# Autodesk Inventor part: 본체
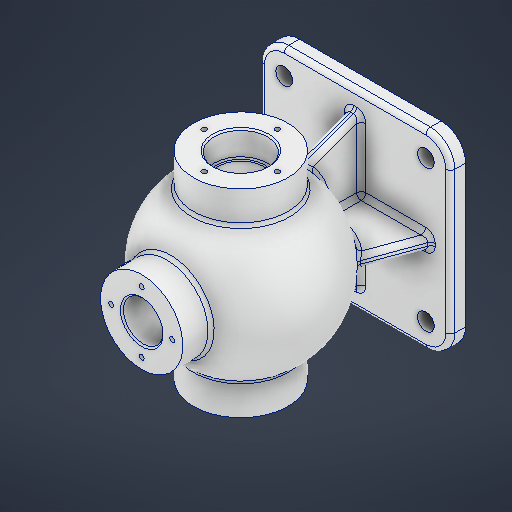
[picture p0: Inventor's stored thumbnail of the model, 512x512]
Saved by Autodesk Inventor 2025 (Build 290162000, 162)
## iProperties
Created: 2025-08
Part Number: 본체
Material: 알루미늄 6061
Document SubType Name: Modeling
Designer: infra006
Density: 2.7 g/cm^3
Appearance: 알루미늄 - 평지
Mass: 1536.91 g
Surface Area: 1167.84 cm^2
Volume: 569.226 cm^3
Author: infra006
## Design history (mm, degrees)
sketch "스케치1"
  geometry: L1 (-46.5, 62.5)-(46.5, 62.5); L2 (62.5, 46.5)-(62.5, -46.5); L3 (46.5, -62.5)-(-46.5, -62.5); L4 (-62.5, -46.5)-(-62.5, 46.5); L5 (-62.5, 62.5)-(62.5, -62.5); L6 (62.5, 62.5)-(-62.5, -62.5); A1 r 16 centre (-46.5, 46.5) between (-46.5, 62.5) and (-62.5, 46.5); A2 r 16 centre (-46.5, -46.5) between (-62.5, -46.5) and (-46.5, -62.5); A3 r 16 centre (46.5, -46.5) between (46.5, -62.5) and (62.5, -46.5); A4 r 16 centre (46.5, 46.5) between (62.5, 46.5) and (46.5, 62.5); 1 further point
  constraints: 12 end point, 8 point on circle, 8 point on line, 8 tangent, 4 centre point, 3 equal radius, 2 midpoint, 2 parallel, 1 horizontal, 1 perpendicular
  dimensions: "d0" = 125 distance of L5.end L6.end; "d1" = 125 distance of L6.start L5.end; "d2" = 16 radius of A1
extrude "돌출1" new body sketch "스케치1" distance "d3" = 10; taper "d4" = 0 deg
node "작업 평면1"
sketch "스케치2"
  geometry: L1 (-54, 0)-(54, 0); L2 (62.5, -46.5)-(62.5, 46.5) reference; L3 (46.5, 62.5)-(-46.5, 62.5) reference; A1 r 54 centre (0, 0) between (-54, 0) and (54, 0); 1 further point
  constraints: 2 end point, 2 point on circle, 1 centre point, 1 coincident, 1 perpendicular
  dimensions: "d8" = 108 diameter of A1; "d9" = 62.5 distance between parallel lines of L3 L1
revolve "회전1" sketch "스케치2" stored, may be unused: angle "d10" = 90 deg
sketch "스케치3"
  geometry: L1 (46.5, 10)-(-46.5, 10) reference; L2 (-37.385, 46.034)-(-50.5, 10); L3 (37.385, 46.034)-(50.5, 10); L4 (62.5, 0)-(62.5, 10) reference; L5 (-62.5, 0)-(-62.5, 10) reference; L6 (37.385, 46.034)-(-37.385, 46.034); L7 (-50.5, 10)-(50.5, 10); L8 (-46.5, 10)-(-62.5, 10) reference; C1 r 54 at (0, 85) reference; A1 r 54 centre (0, 85) between (-37.385, 46.034) and (37.385, 46.034) reference; 5 further points
  constraints: 8 end point, 2 point on circle, 2 point on line, 1 collinear
  dimensions: "d11" = 12 distance from line of L4 L3.end; "d12" = 12 distance from line of L5 L2.end; "d13" = 20 deg angle of L4 L3; "d14" = 20 deg angle of L5 L2
extrude "돌출2" join sketch "스케치3" stored distance "d15" = 8; taper "d16" = 0 deg
sketch "스케치4"
  geometry: L1 (-46.5, 10)-(46.5, 10) reference; L2 (-46.5, 10)-(-62.5, 10) reference; L3 (-37.385, 46.034)-(-50.5, 10); L4 (-62.5, 0)-(-62.5, 10) reference; L5 (37.385, 46.034)-(50.5, 10); L6 (62.5, 0)-(62.5, 10) reference; C1 r 54 at (0, 85) reference; A1 r 54 centre (0, 85) between (-37.385, 46.034) and (37.385, 46.034) reference; 2 further points
  constraints: 4 end point, 2 point on circle, 2 point on line
  dimensions: "d17" = 12 distance from line of L4 L3.end; "d18" = 20 deg angle of L4 L3; "d19" = 12 distance from line of L6 L5.end; "d20" = 20 deg angle of L6 L5
feature "리브1" dims "d21" = 1, "d22" = 8, "d23" = 0, "d24" = 0, "d25" = 1, "d26" = 1
feature "리브2" dims "d27" = 1, "d28" = 8, "d29" = 0, "d30" = 0, "d31" = 1, "d32" = 1
node "작업 평면2"
sketch "스케치7"
  geometry: L1 (65, 116)-(-65, 116); L2 (-65, 116)-(-65, 54); L3 (-65, 54)-(65, 54); L4 (65, 54)-(65, 116); L5 (46.5, 0)-(-46.5, 0) reference; L6 (65, 85)-(-65, 85); L7 (65, 102.5)-(49, 102.5); L8 (49, 102.5)-(49, 100); L9 (49, 100)-(-49, 100); L10 (-49, 102.5)-(-65, 102.5); L11 (-49, 102.5)-(-49, 100); 2 further points
  constraints: 20 end point, 4 parallel, 3 midpoint, 2 horizontal, 2 perpendicular, 2 point on line, 2 vertical
  dimensions: "d38" = 130 distance of L3.end L2.end; "d39" = 62 distance of L2.end L1.end; "d40" = 54 distance between parallel lines of L5 L3; "d41" = 65 distance from line of point (0, 0) L2; "d42" = 17.5 distance between parallel lines of L6 L7; "d43" = 16 distance of L7.start L7.end; "d44" = 2.5 distance of L7.end L8.end; "d45" = 16 distance between parallel lines of L2 L11; "d46" = 17.5 distance between parallel lines of L6 L10
sketch "스케치8"
  geometry: L1 (65, 116)-(-65, 116) reference; L2 (-65, 116)-(-65, 54) reference; L3 (-49, 102.5)-(-65, 102.5) reference; L4 (-49, 102.5)-(-49, 100) reference; L5 (49, 100)-(-49, 100) reference; L6 (49, 102.5)-(49, 100) reference; L7 (65, 102.5)-(49, 102.5) reference; L8 (65, 54)-(65, 116) reference; L9 (65, 85)-(-65, 85) reference; 1 further point
revolve "회전3" stored, may be unused: angle "d47" = 90 deg
sketch "스케치9"
  geometry: L1 (27, 150)-(-27, 150); L2 (46.5, 0)-(-46.5, 0) reference; L3 (27, 150)-(27, 92.205); L4 (27, 92.205)-(-27, 92.205); L5 (-27, 92.205)-(-27, 150); L6 (13, 150)-(13, 92.205); L7 (-13, 150)-(-13, 92.205); L8 (0, 150)-(0, 92.205); 2 further points
  constraints: 14 end point, 4 point on line, 3 midpoint, 2 perpendicular, 2 vertical, 1 horizontal, 1 parallel
  dimensions: "d48" = 150 distance between parallel lines of L2 L1; "d49" = 54 distance of L1.start L1.end; "d50" = 27 horizontal distance of point (0, 0) L1.end; "d51" = 13 distance from line of L8.start L6; "d52" = 26 distance between parallel lines of L6 L7; "d60" = 57.7948 distance between parallel lines of L1 L4
revolve "회전4" stored, may be unused: angle "d53" = 90 deg
sketch "스케치10" dims "d54" = 88
  geometry: L1 (44, 0)-(-95.364, 0); 3 further points
  constraints: 2 end point, 1 coincident, 1 horizontal, 3 other
  dimensions: "d55" = 139.36443 distance of L1.start L1.end; "d56" = 0 distance from line of point (0, 0) L1
revolve "회전5" sketch "스케치10" stored, may be unused: angle "d57" = 90 deg
revolve "회전6" stored, may be unused: angle "d58" = 90 deg
revolve "회전7" stored, may be unused: angle "d59" = 90 deg
sketch "스케치11"
  geometry: L1 (-46.5, -85)-(46.5, -85) reference; L2 (62.5, -85)-(62.5, -75) reference; L3 (0, 24)-(0, -24); L4 (-24, 0)-(24, 0); A1 r 24 centre (0, 0) between (0, 24) and (0, -24); 5 further points
  constraints: 4 coincident, 4 end point, 4 point on circle, 1 centre point, 1 horizontal, 1 vertical
  dimensions: "d61" = 48 diameter of A1; "d62" = 85 distance from line of L1 A1.centre; "d63" = 62.5 distance from line of L2 A1.centre; "d64" = 48 distance of L3.start L3.end; "d65" = 48 distance of L4.start L4.end
hole "구멍1" sketch "스케치11" at (0, 24), (-24, 0), (0, -24), (24, 0) diameter "d66" = 3.242; stored, may be unused: countersink angle "d70" = 90 deg, drill point angle "d72" = 118 deg; dims "d67" = 12, "d68" = 4, "d69" = 2, "d71" = 15
sketch "스케치12"
  geometry: L1 (46.5, 85)-(-46.5, 85) reference; L2 (-62.5, 85)-(-62.5, 75) reference; L3 (0, -24)-(0, 24); L4 (24, 0)-(-24, 0); C1 r 1.621 at (0, 24) reference; C2 r 1.621 at (24, 0) reference; C3 r 1.621 at (0, -24) reference; A1 r 24 centre (0, 0) between (0, -24) and (-24, 0); 5 further points
  constraints: 4 coincident, 4 end point, 2 point on circle, 1 centre point, 1 horizontal, 1 vertical
  dimensions: "d73" = 48 diameter of A1; "d74" = 85 distance from line of L1 A1.centre; "d75" = 62.5 distance from line of L2 A1.centre
hole "구멍2" sketch "스케치12" at (0, -24), (24, 0), (0, 24), (-24, 0) diameter "d76" = 3.242; stored, may be unused: countersink angle "d80" = 90 deg, drill point angle "d82" = 118 deg; dims "d77" = 12, "d78" = 4, "d79" = 2, "d81" = 15
sketch "스케치13"
  geometry: L1 (0, -20)-(0, 20); L2 (-4, 0)-(-37.385, 0) reference; L3 (-20, 0)-(20, 0); A1 r 20 centre (0, 0) between (0, -20) and (0, 20); 5 further points
  constraints: 5 coincident, 4 end point, 4 point on circle, 2 point on line, 1 centre point, 1 perpendicular
  dimensions: "d83" = 40 diameter of A1; "d84" = 40 distance of L1.start L1.end
hole "구멍3" sketch "스케치13" at (0, -20), (20, 0), (0, 20), (-20, 0) diameter "d85" = 3.242; stored, may be unused: countersink angle "d89" = 90 deg, drill point angle "d91" = 118 deg; dims "d86" = 9, "d87" = 4, "d88" = 2, "d90" = 11
node "작업 평면3"
sketch "스케치14"
  geometry: L1 (-14.253, 146.239)-(14.253, 146.239); L2 (14.253, 146.239)-(14.253, 135.761); L3 (14.253, 135.761)-(-14.253, 135.761); L4 (-14.253, 135.761)-(-14.253, 146.239); L5 (-14.253, 141)-(14.253, 141); L6 (0, 146.239)-(0, 135.761); L7 (27, 150)-(-27, 150) reference; L8 (65, 116)-(65, 54) reference; 1 further point
  constraints: 4 end point, 4 midpoint, 2 other
  dimensions: "d93" = 9 distance between parallel lines of L5 L7; "d94" = 65 distance between parallel lines of L8 L6
feature "엠보싱1" sketch "스케치14" dims "d95" = 0.5, "d96" = 0
chamfer "모따기1" distance "d97" = 1; stored, may be unused: second distance "d98" = 2, angle "d99" = 45 deg
chamfer "모따기2" distance "d100" = 1; stored, may be unused: second distance "d101" = 2, angle "d102" = 45 deg
fillet "모깎기1" dims "d103" = 0.6
chamfer "모따기3" distance "d104" = 1; stored, may be unused: second distance "d105" = 2, angle "d106" = 45 deg
feature "면 삭제1"
feature "면 삭제2"
fillet "모깎기2" dims "d107" = 3
fillet "모깎기3" dims "d108" = 3
feature "면 삭제3"
feature "면 삭제4"
fillet "모깎기4" dims "d109" = 3
fillet "모깎기5" dims "d110" = 3
fillet "모깎기6" dims "d111" = 3
sketch "스케치15"
  geometry: L1 (46.5, 46.5)-(-46.5, 46.5); L2 (-46.5, 46.5)-(-46.5, -46.5); L3 (-46.5, -46.5)-(46.5, -46.5); L4 (46.5, -46.5)-(46.5, 46.5); L5 (46.5, 46.5)-(-46.5, -46.5); L6 (-46.5, 46.5)-(46.5, -46.5); A1 r 13 centre (46.5, 46.5) between (59.5, 46.5) and (46.5, 59.5) reference; 5 further points
  constraints: 12 end point, 4 coincident, 2 midpoint, 2 parallel, 1 horizontal, 1 perpendicular
  dimensions: "d112" = 93 distance of L3.end L2.end; "d113" = 93 distance of L2.end L1.end
hole "구멍4" sketch "스케치15" at (46.5, 46.5), (-46.5, 46.5), (-46.5, -46.5), (46.5, -46.5) diameter "d114" = 11; stored, may be unused: countersink angle "d118" = 90 deg, drill point angle "d120" = 118 deg; dims "d115" = 9, "d116" = 4, "d117" = 2, "d119" = 11
feature "ԏ耀ԑ耀ԓ耀ԕ耀ԗ耀ԙ耀ԛ耀ԝ耀" dims "d0" = 125, "d1" = 125, "d2" = 16, "d3" = 10, "d4" = 0, "d5" = 85, "d8" = 108, "d9" = 62.5, "d10" = 90 deg, "d11" = 12, "d12" = 12, "d13" = 20 deg, "d14" = 20 deg, "d15" = 8, "d16" = 0, "d17" = 12, "d18" = 20 deg, "d19" = 12, "d20" = 20 deg, "d21" = 1, "d22" = 8, "d23" = 0, "d24" = 0, "d25" = 1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
node "솔리드1"
feature "A9D066F2-1C7D-4E18-AEED-F7BC21143FA4" dims "d114" = 11, "d115" = 9, "d116" = 4, "d117" = 2, "d118" = 90 deg, "d119" = 11, "d120" = 118 deg
